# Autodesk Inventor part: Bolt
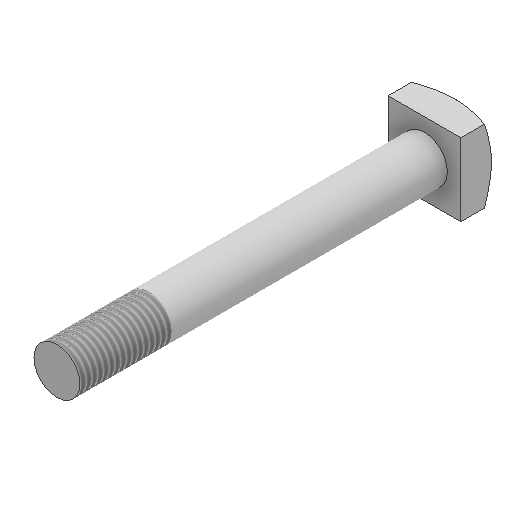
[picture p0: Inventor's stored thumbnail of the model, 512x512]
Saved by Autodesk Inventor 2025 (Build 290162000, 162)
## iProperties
Created: 2016-05
Part Number: Bolt
Material: Generic
Document SubType Name: Modeling
Designer: CADCIM
Density: 1 g/cm^3
Appearance: Default
Author: CADCIM
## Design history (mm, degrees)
sketch "Sketch1"
  geometry: L1 (9.5, 9.5)-(-9.5, 9.5); L2 (-9.5, 9.5)-(-9.5, -9.5); L3 (-9.5, -9.5)-(9.5, -9.5); L4 (9.5, -9.5)-(9.5, 9.5); L5 (0, 0)-(0, 14.108); L6 (0, 0)-(-17.802, 0)
  constraints: 12 end point, 2 horizontal, 2 parallel, 2 perpendicular, 1 vertical, 2 other
  dimensions: "d0" = 19 distance of L3.end L1.start
extrude "Extrusion1" new body sketch "Sketch1" distance "d1" = 8; taper "d2" = 0 deg
sketch "Sketch3"
  geometry: L1 (9.5, 9.5)-(-9.5, 9.5) reference; C1 r 9.5 at (0, 0); 1 further point
  constraints: 1 centre point, 1 coincident, 1 tangent
extrude "Extrusion3" sketch "Sketch3" distance "d6" = 96; taper "d7" = 65 deg
sketch "Sketch4"
  geometry: C1 r 6 at (0, 0); 1 further point
  constraints: 1 centre point, 1 coincident
  dimensions: "d10" = 12 diameter of C1
extrude "Extrusion4" join sketch "Sketch4" distance "d11" = 96; taper "d12" = 0 deg
thread "Thread2" dims "d13" = 24, "d14" = 0
body "Solid1"
